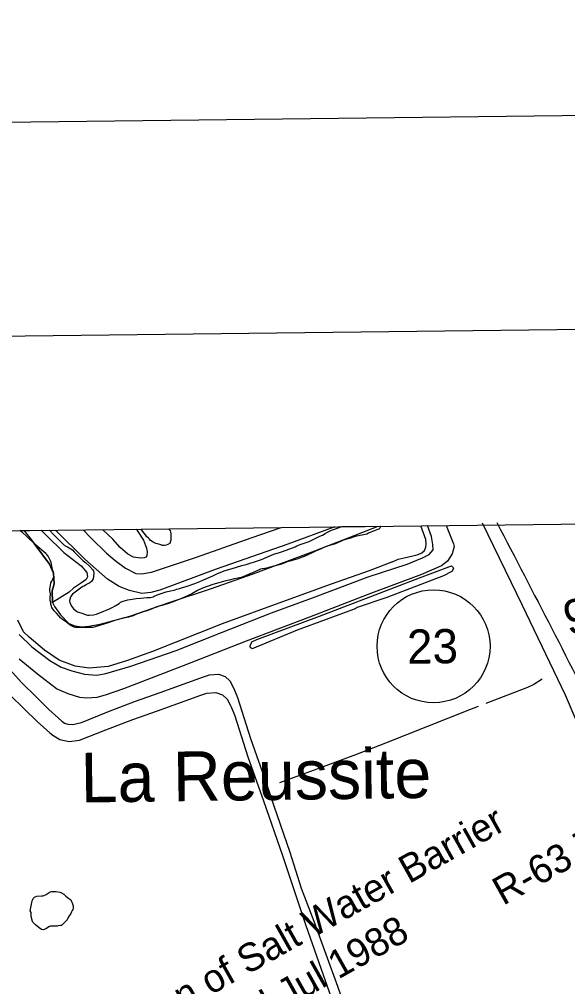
# Model space of a CAD drawing. Extents: x 3694830 to 3732949, y 415201 to 440970.
# Drawn here: x 3706894 to 3708495, y 437561 to 440387 of the extents above; entities that cross this region are included whole.
import ezdxf

# ---------------------------------------------------------------- set-up
doc = ezdxf.new("R2010")
doc.units = 0
for name, color, linetype in [('G-ANNO-NPLT', 7, 'Continuous'), ('V-ANNO-SYMB', 7, 'Continuous'), ('V-GRID-FRAM', 7, 'Continuous'), ('V-LEVE-TOET', 7, 'Continuous'), ('V-RIVR-RANG-IDEN', 7, 'Continuous'), ('V-ROAD-CNTR', 7, 'Continuous'), ('V-ROAD-IDEN', 7, 'Continuous'), ('V-RRAP-SILL-IDEN', 7, 'Continuous'), ('V-SITE-VEGE', 7, 'Continuous'), ('V-SURV-IDEN', 7, 'Continuous'), ('V-TOPO-GNAM-IDEN', 7, 'Continuous'), ('V-TOPO-SHOR', 7, 'Continuous'), ('V-WETL-SWMP', 7, 'Continuous')]:
    doc.layers.add(name, color=color, linetype=linetype)

msp = doc.modelspace()

# ---------------------------------------------------------------- linework, layer by layer
at = {"layer": 'G-ANNO-NPLT'}
msp.add_lwpolyline([(3695701.4, 415784.3), (3732365.5, 416221.6), (3732077.2, 440386.5), (3695413.2, 439949.2)], close=True, dxfattribs=at)
at = {"layer": 'V-ANNO-SYMB'}
msp.add_lwpolyline([(3698443.9, 416442.1), (3731524.7, 416836.6), (3731251.4, 439751.6), (3698170.6, 439357), (3698443.9, 416442.1)], dxfattribs=at)
at = {"layer": 'V-GRID-FRAM'}
msp.add_lwpolyline([(3698844.7, 438797.5), (3730590.8, 439176.2), (3730815.6, 420995.1), (3699053.6, 420616.3), (3698844.7, 438797.5)], dxfattribs=at)
at = {"layer": 'V-LEVE-TOET'}
for points in [[(3708140.6, 438908.4), (3708161.4, 438854.3), (3708163.3, 438846.5), (3708157.4, 438825), (3708144.3, 438803.5), (3708126.4, 438790.3), (3708068.6, 438765), (3707914.9, 438707.8), (3707741.4, 438640.4), (3707556.1, 438570), (3707371.9, 438498.4), (3707197.9, 438431), (3707144.3, 438412.3), (3707119.8, 438405.7), (3707090.6, 438403.8), (3707070.3, 438405.5), (3707036.2, 438416.1), (3707002.8, 438431.5), (3706947.1, 438474.3), (3706893.3, 438517.7)], [(3707815.6, 438904.5), (3707678.1, 438853.9), (3707468.3, 438781), (3707304.4, 438719.6), (3707277.5, 438712.3), (3707251.9, 438709.8), (3707216.1, 438718.7), (3707185.6, 438729.9), (3707151.5, 438751.3), (3707085.1, 438810.1), (3706999.8, 438894.8)], [(3707080.7, 438895.8), (3707102.8, 438872.3), (3707148.3, 438827.7), (3707173.4, 438805.7), (3707203.9, 438783.7), (3707234.4, 438768.3), (3707250.5, 438766.5), (3707279.7, 438772), (3707411.5, 438816), (3707570.6, 438872), (3707658.9, 438902.7)], [(3708097.5, 438876.1), (3708085.9, 438907.8)], [(3706893.6, 438589.9), (3706930.2, 438554.2), (3706983.4, 438513.8), (3707015.7, 438494.2), (3707047.4, 438483.6), (3707084.4, 438474.2), (3707120.2, 438471.3), (3707147, 438475.6), (3707219.8, 438497.3), (3707352.1, 438543.1), (3707483.8, 438595.4), (3707629.8, 438653.2), (3707749.6, 438697.2), (3707912.9, 438758), (3708026.2, 438795.3), (3708071.5, 438813.4), (3708090.5, 438823.6), (3708102.4, 438837.4), (3708101.2, 438852.9), (3708097.5, 438876.1)]]:
    msp.add_lwpolyline(points, dxfattribs=at)
at = {"layer": 'V-ROAD-CNTR'}
msp.add_lwpolyline([(3708245.6, 438915.6), (3708362.4, 438675.8), (3708487.3, 438413.8), (3708667.9, 437991), (3708771.3, 437731.6), (3708825.8, 437602.8)], dxfattribs=at)
msp.add_spline([(3708288, 438916.9), (3708448.6, 438607.2), (3708605.9, 438292.4), (3708766.7, 437932.9), (3708892.4, 437628)], degree=3, dxfattribs=at)
at = {"layer": 'V-ROAD-IDEN'}
msp.add_circle((3708103.5, 438555.3), 165, dxfattribs=at)
at = {"layer": 'V-SITE-VEGE'}
for p, q in [((3706907, 438893.7), (3706982.4, 438894.6)), ((3706912, 438889), (3706907, 438893.7)), ((3706921.9, 438877.3), (3706912, 438889)), ((3706982.4, 438894.6), (3706994.9, 438880.4)), ((3706994.9, 438880.4), (3707021.6, 438853.8)), ((3707249.5, 438897.8), (3707330.9, 438898.8)), ((3707250.9, 438895.7), (3707249.5, 438897.8)), ((3707262.5, 438880.4), (3707250.9, 438895.7)), ((3707265.3, 438875.6), (3707262.5, 438880.4)), ((3707330.9, 438898.8), (3707331.5, 438896.9)), ((3707331.5, 438896.9), (3707334.4, 438892.2)), ((3707334.4, 438892.2), (3707335.4, 438888.3)), ((3707335.4, 438888.3), (3707336.4, 438883.5)), ((3707336.4, 438883.5), (3707336.4, 438865.3)), ((3707771.5, 438876.8), (3707779.5, 438880.1)), ((3707779.5, 438880.1), (3707787, 438884.4)), ((3707787, 438884.4), (3707794, 438888.6)), ((3707794, 438888.6), (3707805.7, 438894.7)), ((3707805.7, 438894.7), (3707820.2, 438899.5)), ((3707820.2, 438899.5), (3707830.4, 438903.2)), ((3707830.4, 438903.2), (3707835.7, 438904.8)), ((3707835.7, 438904.8), (3707948.6, 438906.1)), ((3707894.7, 438880), (3707878.7, 438877.2)), ((3707898.9, 438881), (3707894.7, 438880)), ((3707908.7, 438882.9), (3707898.9, 438881)), ((3707913.8, 438885.7), (3707908.7, 438882.9)), ((3707920.4, 438888.5), (3707913.8, 438885.7)), ((3707925.1, 438890.4), (3707920.4, 438888.5)), ((3707933, 438893.3), (3707925.1, 438890.4)), ((3707937.7, 438895.2), (3707933, 438893.3)), ((3707943.3, 438897.5), (3707937.7, 438895.2)), ((3707946.6, 438900.8), (3707943.3, 438897.5)), ((3707947.9, 438903.6), (3707946.6, 438900.8)), ((3707948.6, 438906.1), (3707947.9, 438903.6)), ((3706926.6, 438870.8), (3706921.9, 438877.3)), ((3706937.4, 438856.3), (3706926.6, 438870.8)), ((3706940.7, 438852.6), (3706937.4, 438856.3)), ((3706952.4, 438842.3), (3706940.7, 438852.6)), ((3707021.6, 438853.8), (3707024, 438851.9)), ((3707024, 438851.9), (3707025.9, 438851)), ((3707271.1, 438870.8), (3707265.3, 438875.6)), ((3707274, 438868), (3707271.1, 438870.8)), ((3707276.9, 438864.1), (3707274, 438868)), ((3707281.7, 438861.3), (3707276.9, 438864.1)), ((3707284.6, 438859.3), (3707281.7, 438861.3)), ((3707292.3, 438855.5), (3707284.6, 438859.3)), ((3707297.1, 438854.6), (3707292.3, 438855.5)), ((3707303.8, 438852.7), (3707297.1, 438854.6)), ((3707309.6, 438850.8), (3707303.8, 438852.7)), ((3707327.8, 438852.8), (3707323, 438850.8)), ((3707334.5, 438856.6), (3707327.8, 438852.8)), ((3707336.4, 438865.3), (3707334.5, 438859.5)), ((3707334.5, 438859.5), (3707334.5, 438856.6)), ((3707704.2, 438848.5), (3707716.4, 438853.7)), ((3707716.4, 438853.7), (3707725.7, 438856.5)), ((3707725.7, 438856.5), (3707739.8, 438861.3)), ((3707739.8, 438861.3), (3707748.2, 438865.5)), ((3707748.2, 438865.5), (3707771.5, 438876.8)), ((3707806.3, 438852.1), (3707793.2, 438847.9)), ((3707814.2, 438854), (3707806.3, 438852.1)), ((3707831.5, 438861.1), (3707814.2, 438854)), ((3707837.6, 438863.9), (3707831.5, 438861.1)), ((3707843.7, 438865.8), (3707837.6, 438863.9)), ((3707856.8, 438870.5), (3707843.7, 438865.8)), ((3707860.5, 438871.5), (3707856.8, 438870.5)), ((3707871.3, 438875.3), (3707860.5, 438871.5)), ((3707878.7, 438877.2), (3707871.3, 438875.3)), ((3706959.9, 438836.3), (3706952.4, 438842.3)), ((3706971.2, 438826.5), (3706959.9, 438836.3)), ((3706973.1, 438824.6), (3706971.2, 438826.5)), ((3706977.8, 438818.1), (3706973.1, 438824.6)), ((3707025.9, 438851), (3707028.2, 438848.7)), ((3707028.2, 438848.7), (3707034.3, 438845.4)), ((3707034.3, 438845.4), (3707048.9, 438837)), ((3707048.9, 438837), (3707054.5, 438831)), ((3707054.5, 438831), (3707063.4, 438821.6)), ((3707311.5, 438849.8), (3707309.6, 438850.8)), ((3707318.2, 438849.9), (3707311.5, 438849.8)), ((3707323, 438850.8), (3707318.2, 438849.9)), ((3707616.3, 438815.9), (3707637.4, 438824)), ((3707637.4, 438824), (3707653.3, 438829.6)), ((3707653.3, 438829.6), (3707662.1, 438832)), ((3707662.1, 438832), (3707699.1, 438846.2)), ((3707699.1, 438846.2), (3707704.2, 438848.5)), ((3707754.8, 438830.9), (3707730.1, 438819.6)), ((3707759, 438833.2), (3707754.8, 438830.9)), ((3707768.9, 438837), (3707759, 438833.2)), ((3707773.1, 438839.4), (3707768.9, 438837)), ((3707785.2, 438845), (3707773.1, 438839.4)), ((3707793.2, 438847.9), (3707785.2, 438845)), ((3706985.3, 438805), (3706977.8, 438818.1)), ((3706986.7, 438800.3), (3706985.3, 438805)), ((3706989.6, 438784.4), (3706986.7, 438800.3)), ((3707063.4, 438821.6), (3707070.5, 438814.6)), ((3707070.5, 438814.6), (3707080.8, 438805.3)), ((3707080.8, 438805.3), (3707088.3, 438799.2)), ((3707088.3, 438799.2), (3707097.2, 438791.3)), ((3707556, 438794.2), (3707592.5, 438805.5)), ((3707592.5, 438805.5), (3707600.9, 438808.9)), ((3707600.9, 438808.9), (3707616.3, 438815.9)), ((3707659, 438795.5), (3707641.2, 438790.3)), ((3707668.8, 438798.8), (3707659, 438795.5)), ((3707676.3, 438802.1), (3707668.8, 438798.8)), ((3707688, 438804.9), (3707676.3, 438802.1)), ((3707700.1, 438808.7), (3707688, 438804.9)), ((3707705.3, 438810.1), (3707700.1, 438808.7)), ((3707714.6, 438813.9), (3707705.3, 438810.1)), ((3707730.1, 438819.6), (3707714.6, 438813.9)), ((3706991.5, 438776.4), (3706989.6, 438784.4)), ((3706993.4, 438771.8), (3706991.5, 438776.4)), ((3706994.8, 438767.1), (3706993.4, 438771.8)), ((3706994.3, 438759.6), (3706994.8, 438767.1)), ((3707097.2, 438791.3), (3707100, 438788)), ((3707100, 438788), (3707109, 438778.7)), ((3707109, 438778.7), (3707110.9, 438775.4)), ((3707111.3, 438769.8), (3707110.4, 438759)), ((3707110.9, 438775.4), (3707111.3, 438769.8)), ((3707468.5, 438765.8), (3707470.9, 438767.2)), ((3707470.9, 438767.2), (3707491.9, 438775.3)), ((3707491.9, 438775.3), (3707501.3, 438778.6)), ((3707501.3, 438778.6), (3707512.5, 438781.4)), ((3707512.5, 438781.4), (3707543.4, 438790.9)), ((3707543.4, 438790.9), (3707556, 438794.2)), ((3707569.2, 438768), (3707554.2, 438761.4)), ((3707572.9, 438769.4), (3707569.2, 438768)), ((3707577.1, 438770.9), (3707572.9, 438769.4)), ((3707594.4, 438778.9), (3707577.1, 438770.9)), ((3707598.2, 438780.3), (3707594.4, 438778.9)), ((3707602.9, 438781.2), (3707598.2, 438780.3)), ((3707610.8, 438782.7), (3707602.9, 438781.2)), ((3707613.1, 438782.7), (3707610.8, 438782.7)), ((3707622.5, 438785.5), (3707613.1, 438782.7)), ((3707641.2, 438790.3), (3707622.5, 438785.5)), ((3706984.6, 438732.9), (3706986.4, 438740.9)), ((3706986.4, 438740.9), (3706989.2, 438746)), ((3706989.2, 438746), (3706992, 438751.6)), ((3706992, 438751.6), (3706994.3, 438759.6)), ((3707100.2, 438740.8), (3707089.9, 438735.6)), ((3707104.9, 438744.5), (3707100.2, 438740.8)), ((3707109.5, 438752), (3707104.9, 438744.5)), ((3707110.4, 438759), (3707109.5, 438752)), ((3707406.8, 438738.5), (3707420.9, 438744.1)), ((3707420.9, 438744.1), (3707430.2, 438748.4)), ((3707430.2, 438748.4), (3707459.2, 438761.1)), ((3707459.2, 438761.1), (3707468.5, 438765.8)), ((3707476.6, 438740.6), (3707459.3, 438735.4)), ((3707496.7, 438746.3), (3707476.6, 438740.6)), ((3707506.5, 438748.6), (3707496.7, 438746.3)), ((3707521.5, 438752), (3707506.5, 438748.6)), ((3707532.3, 438753.9), (3707521.5, 438752)), ((3707542.1, 438756.2), (3707532.3, 438753.9)), ((3707554.2, 438761.4), (3707542.1, 438756.2)), ((3706982.8, 438717.4), (3706983.2, 438723.5)), ((3706983.7, 438713.2), (3706982.8, 438717.4)), ((3706983.2, 438723.5), (3706984.6, 438732.9)), ((3706985.1, 438709), (3706983.7, 438713.2)), ((3707056.7, 438713.9), (3707049.3, 438707.8)), ((3707072.6, 438724.7), (3707056.7, 438713.9)), ((3707079.6, 438729.9), (3707072.6, 438724.7)), ((3707083.4, 438731.3), (3707079.6, 438729.9)), ((3707089.9, 438735.6), (3707083.4, 438731.3)), ((3707302.1, 438707.7), (3707322.6, 438714.3)), ((3707322.6, 438714.3), (3707335.3, 438717.2)), ((3707335.3, 438717.2), (3707346, 438719.1)), ((3707346, 438719.1), (3707349.3, 438720)), ((3707349.3, 438720), (3707354, 438721.9)), ((3707354, 438721.9), (3707361.9, 438724.3)), ((3707361.9, 438724.3), (3707367.1, 438726.2)), ((3707367.1, 438726.2), (3707384.4, 438730.9)), ((3707384.4, 438730.9), (3707406.8, 438738.5)), ((3707413.9, 438718.4), (3707397.6, 438708.5)), ((3707428.4, 438725.4), (3707413.9, 438718.4)), ((3707459.3, 438735.4), (3707428.4, 438725.4)), ((3706983.8, 438697.8), (3706984.7, 438706.7)), ((3706983.8, 438693.1), (3706983.8, 438697.8)), ((3706984.3, 438689.3), (3706983.8, 438693.1)), ((3706985.7, 438683.3), (3706984.3, 438689.3)), ((3706984.7, 438706.7), (3706985.1, 438709)), ((3706986.2, 438678.6), (3706985.7, 438683.3)), ((3707042.3, 438696.1), (3707040.9, 438688.6)), ((3707040.9, 438688.6), (3707041.9, 438682.5)), ((3707041.9, 438682.5), (3707047.5, 438671.3)), ((3707045.5, 438702.7), (3707042.3, 438696.1)), ((3707049.3, 438707.8), (3707045.5, 438702.7)), ((3707185.6, 438680.6), (3707188.9, 438683.9)), ((3707188.9, 438683.9), (3707197.3, 438687.2)), ((3707197.3, 438687.2), (3707210.4, 438691)), ((3707210.4, 438691), (3707217.9, 438692.4)), ((3707217.9, 438692.4), (3707235.2, 438694.8)), ((3707235.2, 438694.8), (3707248.7, 438695.8)), ((3707248.7, 438695.8), (3707266.5, 438697.8)), ((3707266.5, 438697.8), (3707275.9, 438698.3)), ((3707275.9, 438698.3), (3707284.3, 438700.2)), ((3707284.3, 438700.2), (3707288, 438701.6)), ((3707288, 438701.6), (3707294.1, 438704.4)), ((3707294.1, 438704.4), (3707302.1, 438707.7)), ((3707342.9, 438685.4), (3707329.3, 438680.6)), ((3707374.7, 438697.6), (3707342.9, 438685.4)), ((3707389.2, 438704.2), (3707374.7, 438697.6)), ((3707397.6, 438708.5), (3707389.2, 438704.2)), ((3706988.1, 438672.5), (3706986.2, 438678.6)), ((3706989, 438668.8), (3706988.1, 438672.5)), ((3706995.6, 438658.5), (3706989, 438668.8)), ((3706999.8, 438654.8), (3706995.6, 438658.5)), ((3707002.6, 438652.4), (3706999.8, 438654.8)), ((3707047.5, 438671.3), (3707052.2, 438665.2)), ((3707052.2, 438665.2), (3707061.1, 438657.8)), ((3707061.1, 438657.8), (3707063.5, 438656.4)), ((3707063.5, 438656.4), (3707076.1, 438651.7)), ((3707126.2, 438651.9), (3707138.4, 438657.1)), ((3707138.4, 438657.1), (3707147.7, 438661.3)), ((3707147.7, 438661.3), (3707155.7, 438664.2)), ((3707155.7, 438664.2), (3707167.4, 438669.8)), ((3707167.4, 438669.8), (3707173.9, 438673.1)), ((3707173.9, 438673.1), (3707185.6, 438680.6)), ((3707253.6, 438655.1), (3707250.8, 438653.7)), ((3707258.7, 438657), (3707253.6, 438655.1)), ((3707263.4, 438658.4), (3707258.7, 438657)), ((3707280.2, 438664.1), (3707263.4, 438658.4)), ((3707292.8, 438669.3), (3707280.2, 438664.1)), ((3707301.3, 438672.1), (3707292.8, 438669.3)), ((3707310.1, 438674.5), (3707301.3, 438672.1)), ((3707329.3, 438680.6), (3707310.1, 438674.5)), ((3707009.7, 438644.5), (3707002.6, 438652.4)), ((3707014.9, 438637.5), (3707009.7, 438644.5)), ((3707017.7, 438635.2), (3707014.9, 438637.5)), ((3707020.5, 438633.8), (3707017.7, 438635.2)), ((3707030.3, 438626.8), (3707020.5, 438633.8)), ((3707034.1, 438623.5), (3707030.3, 438626.8)), ((3707076.1, 438651.7), (3707086.9, 438648)), ((3707086.9, 438648), (3707093.5, 438646.6)), ((3707093.5, 438646.6), (3707097.7, 438646.6)), ((3707097.7, 438646.6), (3707110.3, 438647.6)), ((3707110.3, 438647.6), (3707119.2, 438649.5)), ((3707119.2, 438649.5), (3707126.2, 438651.9)), ((3707161, 438626.7), (3707153.5, 438623.9)), ((3707175.5, 438631.5), (3707161, 438626.7)), ((3707179.2, 438632.9), (3707175.5, 438631.5)), ((3707193.7, 438636.7), (3707179.2, 438632.9)), ((3707198.8, 438637.6), (3707193.7, 438636.7)), ((3707212.4, 438640.5), (3707198.8, 438637.6)), ((3707219.4, 438642.4), (3707212.4, 438640.5)), ((3707226, 438644.7), (3707219.4, 438642.4)), ((3707236.3, 438649), (3707226, 438644.7)), ((3707250.8, 438653.7), (3707236.3, 438649)), ((3707037.9, 438621.2), (3707034.1, 438623.5)), ((3707042.5, 438617.4), (3707037.9, 438621.2)), ((3707050.5, 438613.3), (3707042.5, 438617.4)), ((3707053.8, 438611.4), (3707050.5, 438613.3)), ((3707058, 438610), (3707053.8, 438611.4)), ((3707076.3, 438610.1), (3707058, 438610)), ((3707086.6, 438609.2), (3707076.3, 438610.1)), ((3707099.2, 438610.1), (3707086.6, 438609.2)), ((3707108.6, 438610.6), (3707099.2, 438610.1)), ((3707115.1, 438612.1), (3707108.6, 438610.6)), ((3707153.5, 438623.9), (3707115.1, 438612.1))]:
    msp.add_line(p, q, dxfattribs=at)
for points in [[(3707874.1, 438664.9), (3707705.3, 438602.6), (3707573.7, 438548.3), (3707570.7, 438549.5), (3707568.3, 438552.5), (3707567.7, 438556.7), (3707572.4, 438568.1), (3707587.4, 438575.3), (3707770.5, 438643), (3707991.3, 438727.6), (3708061.9, 438755.4), (3708155.8, 438790.5), (3708160.7, 438785.7), (3708161.3, 438782.1), (3708157.1, 438773.7), (3708132.6, 438761.6), (3707967.4, 438697.6), (3707880, 438668.5)], [(3706925.9, 437782.4), (3706931.4, 437812.3), (3706933.3, 437816.1), (3706934.7, 437818.4), (3706936.1, 437820.3), (3706937.9, 437822.2), (3706939.8, 437823.1), (3706945.4, 437825.5), (3706958.5, 437826.5), (3706963.7, 437826.5), (3706972.1, 437830.7), (3706983.7, 437837.8), (3706988.4, 437839.2), (3706997.8, 437838.8), (3707001.1, 437838.8), (3707011.8, 437836.9), (3707015.6, 437836.5), (3707024, 437831.4), (3707029.7, 437825.8), (3707038.6, 437818.8), (3707044.2, 437815), (3707046.1, 437810.4), (3707048.5, 437805.7), (3707050.8, 437796.8), (3707050.8, 437790.7), (3707049.9, 437787), (3707048.5, 437783.2), (3707046.2, 437779.5), (3707044.3, 437775.3), (3707037.4, 437764.9), (3707033.6, 437756.5), (3707031.8, 437754.1), (3707028, 437750.4), (3707020.1, 437742.9), (3707016.8, 437740.1), (3707014, 437740), (3707007.5, 437738.6), (3707004.7, 437738.1), (3706998.1, 437737.7), (3706991.1, 437737.6), (3706987.8, 437738.1), (3706985, 437738.1), (3706982.2, 437736.7), (3706971.5, 437730.1), (3706966.3, 437727.7), (3706964, 437727.2), (3706958.8, 437728.6), (3706951.8, 437732.8), (3706941.5, 437742.2), (3706933.9, 437749.1), (3706932.5, 437751.5), (3706928.3, 437766), (3706928.2, 437778.2)]]:
    msp.add_lwpolyline(points, close=True, dxfattribs=at)
at = {"layer": 'V-TOPO-SHOR'}
for points in [[(3706896.4, 438893.6), (3706900.1, 438891.1), (3706937.7, 438855.7), (3706962.8, 438821.2), (3706982.1, 438795.3), (3706993.7, 438769.4), (3706995.8, 438737.7), (3706990.1, 438717.5), (3706991.2, 438682.9), (3706997, 438671.4), (3707014.3, 438647.4), (3707038.4, 438621.5), (3707055.8, 438614.9), (3707076.9, 438612), (3707097.1, 438614), (3707129.7, 438619.9), (3707217.1, 438643.2), (3707334.2, 438684), (3707452.3, 438722.8), (3707577.1, 438766.5), (3707756.6, 438834.3), (3707874.6, 438879.9), (3707942, 438906)], [(3707234.5, 438897.6), (3707235.9, 438896.2), (3707256.6, 438865.7), (3707265.1, 438842.2), (3707267.2, 438831.7), (3707266, 438819.5), (3707263, 438815.7), (3707258.4, 438813.6), (3707247.9, 438812.3), (3707227.4, 438816), (3707210.5, 438824.8), (3707188.2, 438844), (3707166.7, 438868.3), (3707137.2, 438896.4)], [(3707983.5, 438802.4), (3708000.2, 438810.2), (3708017.6, 438814), (3708042.6, 438819.3), (3708058.9, 438823.8), (3708069.5, 438828.2), (3708077, 438835.5), (3708081.3, 438845), (3708082.3, 438854.9), (3708081.1, 438867.6), (3708066.2, 438907.5)], [(3707983.5, 438802.4), (3707915.4, 438775.3), (3707804, 438736.5), (3707661.9, 438685.1), (3707486.3, 438621.1), (3707282.8, 438539.7), (3707209.9, 438513.5), (3707153.2, 438496), (3707097.5, 438491), (3707057.1, 438497.6), (3707010, 438514.8), (3706967.6, 438544.4), (3706923.2, 438581.7), (3706905.9, 438598), (3706889.5, 438631.6)], [(3706857.8, 438496.9), (3706900.3, 438449.5), (3706943.8, 438406.8), (3706980.5, 438370.8), (3707017.7, 438337.1), (3707026.3, 438330.5)], [(3707026.3, 438330.5), (3707035.4, 438327.6), (3707050.6, 438327.2), (3707075.3, 438333), (3707154.2, 438364.7), (3707233.6, 438394.9), (3707305.3, 438420.4), (3707431.7, 438466), (3707449.3, 438471.7), (3707475.5, 438473.7), (3707495, 438466.7), (3707508.4, 438454.3), (3707520.4, 438432), (3707530.9, 438405.9), (3707569.4, 438285.6), (3707615, 438156.8)], [(3708420.5, 438459.7), (3708396.1, 438444.2), (3708377.5, 438434.7), (3708256.4, 438387.9)], [(3706821.7, 438438.7), (3706828.4, 438440.2), (3706834.6, 438437.8), (3706840.3, 438433.5), (3706865.4, 438414.8), (3706908.9, 438372.1), (3706945.6, 438336.1), (3706982.8, 438302.4), (3706991.4, 438295.8)], [(3707069.9, 438280.8), (3707146.2, 438311.4), (3707225.6, 438341.6), (3707297.4, 438367.1), (3707423.8, 438412.7), (3707441.4, 438418.5), (3707467.5, 438420.5), (3707487, 438413.4), (3707500.4, 438401.1), (3707509.4, 438384.2)], [(3707509.4, 438384.2), (3707512.4, 438378.7), (3707522.9, 438352.6), (3707561.4, 438232.3), (3707607, 438103.5)], [(3708234, 438379.3), (3708208.7, 438369.5), (3707963.1, 438272.5)], [(3706991.4, 438295.8), (3707012, 438283.4), (3707039.7, 438276.8), (3707069.9, 438280.8)], [(3707963.1, 438272.5), (3707875.4, 438238.7), (3707763, 438196.2), (3707654, 438156.5)], [(3707615, 438156.8), (3707637.5, 438089.5), (3707684.1, 437953.8), (3707716.9, 437848.6), (3707754.1, 437752.7), (3707789.3, 437655.8), (3707822.6, 437562.8), (3707857.4, 437464.4), (3707892.2, 437365.1), (3707928.9, 437258.5), (3707954.4, 437176.6), (3707981.8, 437095.7)], [(3707607, 438103.5), (3707662.4, 437944.6), (3707730.5, 437740.1), (3707805.4, 437526.5), (3707860.7, 437375.8), (3707915, 437221.2), (3707965, 437069.5), (3708006.6, 436959.6)]]:
    msp.add_lwpolyline(points, dxfattribs=at)
at = {"layer": 'V-WETL-SWMP'}
for p, q in [((3706896.4, 438893.6), (3706958, 438894.3)), ((3706896.4, 438893.6), (3706958, 438894.3)), ((3706900.1, 438891.1), (3706896.4, 438893.6)), ((3706900.1, 438891.1), (3706896.4, 438893.6)), ((3706937.7, 438855.7), (3706900.1, 438891.1)), ((3706937.7, 438855.7), (3706900.1, 438891.1)), ((3706958, 438894.3), (3706971.3, 438880.5)), ((3706958, 438894.3), (3706971.3, 438880.5)), ((3706971.3, 438880.5), (3707024.4, 438829.1)), ((3706971.3, 438880.5), (3707024.4, 438829.1)), ((3706962.8, 438821.2), (3706937.7, 438855.7)), ((3706962.8, 438821.2), (3706937.7, 438855.7)), ((3707024.4, 438829.1), (3707074.1, 438790.8)), ((3707024.4, 438829.1), (3707074.1, 438790.8)), ((3706982.1, 438795.3), (3706962.8, 438821.2)), ((3706982.1, 438795.3), (3706962.8, 438821.2)), ((3706993.7, 438769.4), (3706982.1, 438795.3)), ((3706993.7, 438769.4), (3706982.1, 438795.3)), ((3706995.8, 438737.7), (3706993.7, 438769.4)), ((3706995.8, 438737.7), (3706993.7, 438769.4)), ((3707074.1, 438790.8), (3707090.6, 438771.1)), ((3707074.1, 438790.8), (3707090.6, 438771.1)), ((3707090.6, 438771.1), (3707093.5, 438758.1)), ((3707090.6, 438771.1), (3707093.5, 438758.1)), ((3707075.3, 438741.1), (3707051.7, 438724.7)), ((3707075.3, 438741.1), (3707051.7, 438724.7)), ((3707088.7, 438750.8), (3707075.3, 438741.1)), ((3707088.7, 438750.8), (3707075.3, 438741.1)), ((3707093.5, 438758.1), (3707088.7, 438750.8)), ((3707093.5, 438758.1), (3707088.7, 438750.8)), ((3706990.1, 438717.5), (3706995.8, 438737.7)), ((3706990.1, 438717.5), (3706995.8, 438737.7)), ((3706991.1, 438683.7), (3706990.1, 438717.5)), ((3706991.1, 438683.7), (3706990.1, 438717.5)), ((3707039.2, 438713.6), (3706991.1, 438683.7)), ((3707039.2, 438713.6), (3706991.1, 438683.7)), ((3707051.7, 438724.7), (3707039.2, 438713.6)), ((3707051.7, 438724.7), (3707039.2, 438713.6))]:
    msp.add_line(p, q, dxfattribs=at)

# ---------------------------------------------------------------- texts
at = {"layer": 'V-RIVR-RANG-IDEN'}
msp.add_text('R-63.7', height=83, rotation=29.2396, dxfattribs=at).set_placement((3708306.3, 437796.8))
at = {"layer": 'V-ROAD-IDEN'}
msp.add_text('23', height=100, rotation=0.7811, dxfattribs=at).set_placement((3708026.6, 438504.2))
at = {"layer": 'V-RRAP-SILL-IDEN'}
for s, rotation, p in [('Location of Salt Water Barrier', 29.3104, (3707064.6, 437317.6)), ('Location of Salt Water Barrier', 29.5409, (3707938.7, 437053.8)), ('Constructed Jul 1988', 29.3104, (3707134.2, 437193.8))]:
    msp.add_text(s, height=82, rotation=rotation, dxfattribs=at).set_placement(p)
at = {"layer": 'V-SURV-IDEN'}
msp.add_text('952+70.0', height=100, rotation=13.7202, dxfattribs=at).set_placement((3708497.1, 438586.8))
at = {"layer": 'V-TOPO-GNAM-IDEN'}
msp.add_text('La Reussite', height=145, rotation=0.7812, dxfattribs=at).set_placement((3707073.7, 438098.9))

doc.saveas('drawing.dxf')
